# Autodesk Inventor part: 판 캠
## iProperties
Company: 한국ATC센터
Created: 2012-05
Part Number: 판 캠
Document SubType Name: 모델링
Designer: KYOUNG IL JANG
Mass: 681.586 g
Surface Area: 331.303 cm^2
Volume: 86.8262 cm^3
Density: 7.85 g/cm^3
Material: 강
변환 표준: STEP AP214IS
파일 이름: C:\Users\SeoGD\Desktop\?쒗뿕\??stp
전처리기: Build: 253, Release: 2010 SP1 - Date: Wed 07/29/2009
전송 단위: 밀리미터
불확실성: 0.01
Author: KYOUNG IL JANG
